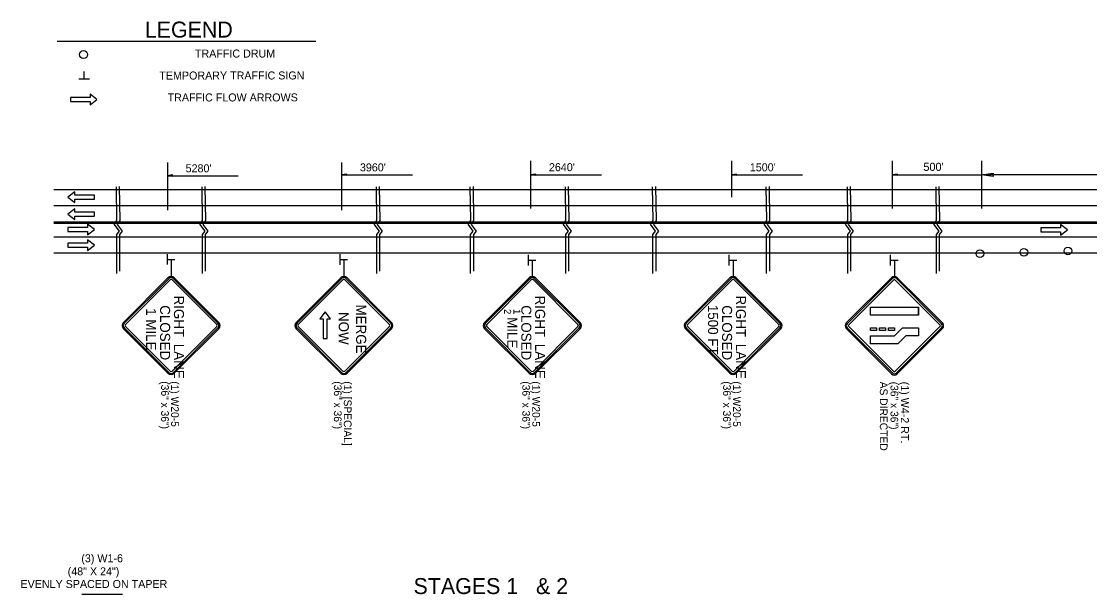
# Model space of a CAD drawing. Extents: x 1930579 to 1937984, y 596452 to 597630.
# Drawn here: x 1933731 to 1934532, y 597187 to 597617 of the extents above; entities that cross this region are included whole.
import ezdxf

# ---------------------------------------------------------------- set-up
doc = ezdxf.new("R2010")
doc.units = 0
for name, color, linetype in [('Default', 7, 'Continuous'), ('P_TC_Signs_Permanent', 7, 'Continuous'), ('P_TC_Signs_Temporary', 7, 'Continuous'), ('R_Border', 7, 'Continuous'), ('R_MOT', 7, 'Continuous'), ('R_Striping', 7, 'Continuous')]:
    doc.layers.add(name, color=color, linetype=linetype)

msp = doc.modelspace()

# ---------------------------------------------------------------- linework, layer by layer
at = {"layer": 'Default'}
for p, q in [((1933840.51, 597510.73), (1933840.51, 597474.82)), ((1933971.24, 597510.73), (1933971.24, 597474.82)), ((1934112.98, 597511.96), (1934112.98, 597476.04)), ((1934263.62, 597511.96), (1934263.62, 597484.57)), ((1934384.19, 597511.96), (1934384.19, 597476.04)), ((1934450.97, 597511.96), (1934450.97, 597476.04)), ((1933844.34, 597501.32), (1933840.51, 597500.75)), ((1933840.51, 597500.75), (1933893.74, 597500.75)), ((1933844.34, 597500.17), (1933840.51, 597500.75)), ((1933844.34, 597501.23), (1933841.15, 597500.75)), ((1933844.34, 597500.27), (1933841.15, 597500.75)), ((1933844.34, 597501.13), (1933841.81, 597500.75)), ((1933844.34, 597500.37), (1933841.81, 597500.75)), ((1933844.34, 597501.03), (1933842.45, 597500.75)), ((1933844.34, 597500.46), (1933842.45, 597500.75)), ((1933844.34, 597500.94), (1933843.09, 597500.75)), ((1933844.34, 597500.56), (1933843.09, 597500.75)), ((1933844.34, 597500.84), (1933843.73, 597500.75)), ((1933844.34, 597500.66), (1933843.73, 597500.75)), ((1933844.34, 597500.17), (1933844.34, 597501.32)), ((1933975.06, 597502), (1933971.24, 597501.43)), ((1933971.24, 597501.43), (1934024.47, 597501.43)), ((1933975.06, 597500.85), (1933971.24, 597501.43)), ((1933975.06, 597501.91), (1933971.88, 597501.43)), ((1933975.06, 597500.95), (1933971.88, 597501.43)), ((1933975.06, 597501.81), (1933972.53, 597501.43)), ((1933975.06, 597501.05), (1933972.53, 597501.43)), ((1933975.06, 597501.71), (1933973.17, 597501.43)), ((1933975.06, 597501.14), (1933973.17, 597501.43)), ((1933975.06, 597501.62), (1933973.82, 597501.43)), ((1933975.06, 597501.24), (1933973.82, 597501.43)), ((1933975.06, 597501.52), (1933974.46, 597501.43)), ((1933975.06, 597501.34), (1933974.46, 597501.43)), ((1933975.06, 597500.85), (1933975.06, 597502)), ((1934116.81, 597502), (1934112.98, 597501.43)), ((1934112.98, 597501.43), (1934166.22, 597501.43)), ((1934116.81, 597500.85), (1934112.98, 597501.43)), ((1934116.81, 597501.91), (1934113.62, 597501.43)), ((1934116.81, 597500.95), (1934113.62, 597501.43)), ((1934116.81, 597501.81), (1934114.28, 597501.43)), ((1934116.81, 597501.05), (1934114.28, 597501.43)), ((1934116.81, 597501.71), (1934114.92, 597501.43)), ((1934116.81, 597501.14), (1934114.92, 597501.43)), ((1934116.81, 597501.62), (1934115.57, 597501.43)), ((1934116.81, 597501.24), (1934115.57, 597501.43)), ((1934116.81, 597501.52), (1934116.2, 597501.43)), ((1934116.81, 597501.34), (1934116.2, 597501.43)), ((1934116.81, 597500.85), (1934116.81, 597502)), ((1934267.45, 597502), (1934263.62, 597501.43)), ((1934263.62, 597501.43), (1934316.85, 597501.43)), ((1934267.45, 597500.85), (1934263.62, 597501.43)), ((1934267.45, 597501.91), (1934264.26, 597501.43)), ((1934267.45, 597500.95), (1934264.26, 597501.43)), ((1934267.45, 597501.81), (1934264.92, 597501.43)), ((1934267.45, 597501.05), (1934264.92, 597501.43)), ((1934267.45, 597501.71), (1934265.55, 597501.43)), ((1934267.45, 597501.14), (1934265.55, 597501.43)), ((1934267.45, 597501.62), (1934266.2, 597501.43)), ((1934267.45, 597501.24), (1934266.2, 597501.43)), ((1934267.45, 597501.52), (1934266.84, 597501.43)), ((1934267.45, 597501.34), (1934266.84, 597501.43)), ((1934267.45, 597500.85), (1934267.45, 597502)), ((1934388.01, 597502), (1934384.19, 597501.43)), ((1934384.19, 597501.43), (1934450.97, 597501.43)), ((1934388.01, 597500.85), (1934384.19, 597501.43)), ((1934388.01, 597501.91), (1934384.83, 597501.43)), ((1934388.01, 597500.95), (1934384.83, 597501.43)), ((1934388.01, 597501.81), (1934385.48, 597501.43)), ((1934388.01, 597501.05), (1934385.48, 597501.43)), ((1934388.01, 597501.71), (1934386.12, 597501.43)), ((1934388.01, 597501.14), (1934386.12, 597501.43)), ((1934388.01, 597501.62), (1934386.77, 597501.43)), ((1934388.01, 597501.24), (1934386.77, 597501.43)), ((1934388.01, 597501.52), (1934387.41, 597501.43)), ((1934388.01, 597501.34), (1934387.41, 597501.43)), ((1934388.01, 597500.85), (1934388.01, 597502)), ((1934450.97, 597501.43), (1934459.83, 597502.76)), ((1934818.18, 597501.43), (1934450.97, 597501.43)), ((1934459.83, 597500.1), (1934450.97, 597501.43)), ((1934459.83, 597502.76), (1934459.83, 597500.1)), ((1935069.92, 597490.19), (1933755.41, 597490.19)), ((1935069.92, 597478.19), (1933755.41, 597478.19)), ((1935069.92, 597465.96), (1933755.41, 597465.96)), ((1935069.92, 597464.81), (1933755.41, 597464.81)), ((1935069.92, 597454.63), (1933755.41, 597454.63)), ((1935069.92, 597442.63), (1933755.41, 597442.63)), ((1933840.51, 597434.03), (1933840.51, 597442.01)), ((1933840.63, 597438), (1933846.08, 597438)), ((1933970.06, 597433.97), (1933970.06, 597441.95)), ((1933970.18, 597437.94), (1933975.63, 597437.94)), ((1934111.37, 597433.52), (1934111.37, 597441.5)), ((1934111.48, 597437.49), (1934116.93, 597437.49)), ((1934261.94, 597433.52), (1934261.94, 597441.5)), ((1934262.06, 597437.49), (1934267.51, 597437.49)), ((1934382.9, 597433.52), (1934382.9, 597441.5)), ((1934383.02, 597437.49), (1934388.47, 597437.49))]:
    msp.add_line(p, q, dxfattribs=at)
for points in [[(1933804.45, 597492.71), (1933804.84, 597467.14), (1933802.89, 597464.24), (1933806.68, 597459.04), (1933804.68, 597456.64), (1933804.68, 597429.08)], [(1933868.69, 597492.71), (1933869.08, 597467.14), (1933867.13, 597464.24), (1933870.92, 597459.04), (1933868.93, 597456.64), (1933868.92, 597429.08)], [(1933999.41, 597492.71), (1933999.8, 597467.14), (1933997.85, 597464.24), (1934001.65, 597459.04), (1933999.65, 597456.64), (1933999.65, 597429.08)], [(1934069.8, 597492.71), (1934070.18, 597467.14), (1934068.24, 597464.24), (1934072.03, 597459.04), (1934070.03, 597456.64), (1934070.03, 597429.08)], [(1934141.16, 597492.71), (1934141.55, 597467.14), (1934139.6, 597464.24), (1934143.4, 597459.04), (1934141.4, 597456.64), (1934141.39, 597429.08)], [(1934206.6, 597492.71), (1934206.99, 597467.14), (1934205.04, 597464.24), (1934208.84, 597459.04), (1934206.84, 597456.64), (1934206.84, 597429.08)], [(1934291.8, 597492.71), (1934292.18, 597467.14), (1934290.24, 597464.24), (1934294.03, 597459.04), (1934292.03, 597456.64), (1934292.03, 597429.08)], [(1934352.68, 597492.71), (1934353.07, 597467.14), (1934351.12, 597464.24), (1934354.92, 597459.04), (1934352.92, 597456.64), (1934352.91, 597429.08)], [(1934419.14, 597492.71), (1934419.53, 597467.14), (1934417.58, 597464.24), (1934421.37, 597459.04), (1934419.37, 597456.64), (1934419.37, 597429.08)], [(1933802.05, 597492.48), (1933802.44, 597467.24), (1933800.49, 597464.34), (1933804.29, 597459.14), (1933802.29, 597456.74), (1933802.28, 597427.4)], [(1933866.3, 597492.48), (1933866.68, 597467.24), (1933864.73, 597464.34), (1933868.53, 597459.14), (1933866.53, 597456.74), (1933866.52, 597427.4)], [(1933997.02, 597492.48), (1933997.4, 597467.24), (1933995.46, 597464.34), (1933999.25, 597459.14), (1933997.25, 597456.74), (1933997.25, 597427.4)], [(1934067.4, 597492.48), (1934067.79, 597467.24), (1934065.84, 597464.34), (1934069.64, 597459.14), (1934067.64, 597456.74), (1934067.63, 597427.4)], [(1934138.77, 597492.48), (1934139.15, 597467.24), (1934137.2, 597464.34), (1934141, 597459.14), (1934139, 597456.74), (1934138.99, 597427.4)], [(1934204.21, 597492.48), (1934204.59, 597467.24), (1934202.64, 597464.34), (1934206.44, 597459.14), (1934204.44, 597456.74), (1934204.44, 597427.4)], [(1934289.4, 597492.48), (1934289.79, 597467.24), (1934287.84, 597464.34), (1934291.64, 597459.14), (1934289.64, 597456.74), (1934289.63, 597427.4)], [(1934350.29, 597492.48), (1934350.67, 597467.24), (1934348.72, 597464.34), (1934352.52, 597459.14), (1934350.52, 597456.74), (1934350.52, 597427.4)], [(1934416.74, 597492.48), (1934417.13, 597467.24), (1934415.18, 597464.34), (1934418.98, 597459.14), (1934416.98, 597456.74), (1934416.97, 597427.4)]]:
    msp.add_lwpolyline(points, dxfattribs=at)
for centre, radius in [((1933777.66, 597591.57), 3), ((1934449.89, 597442.25), 2.87), ((1934482.87, 597443.3), 2.87), ((1934515.86, 597444.34), 2.87)]:
    msp.add_circle(centre, radius, dxfattribs=at)
at = {"layer": 'P_TC_Signs_Permanent'}
for p, q in [((1934349.68, 597390.32), (1934383.62, 597424.26)), ((1934403.75, 597396.24), (1934403.75, 597402.24)), ((1934383.62, 597352.14), (1934349.68, 597386.08)), ((1934421.81, 597386.08), (1934387.87, 597352.14)), ((1933806.82, 597186.52), (1933776.45, 597186.52))]:
    msp.add_line(p, q, dxfattribs=at)
for points in [[(1934384.26, 597423.63), (1934350.32, 597389.68)], [(1934351.38, 597388.62), (1934385.32, 597422.56)], [(1934386.17, 597422.56), (1934420.11, 597388.62)], [(1934421.17, 597389.68), (1934387.23, 597423.63)], [(1934387.87, 597424.26), (1934404.84, 597407.29), (1934421.81, 597390.32)], [(1934350.32, 597386.71), (1934384.26, 597352.77)], [(1934385.32, 597353.83), (1934351.38, 597387.78)], [(1934420.11, 597387.78), (1934386.17, 597353.83)], [(1934387.23, 597352.77), (1934421.17, 597386.71)]]:
    msp.add_lwpolyline(points, dxfattribs=at)
for points in [[(1934367.75, 597396.24), (1934367.75, 597402.24), (1934403.75, 597402.24), (1934403.75, 597396.24)], [(1934367.75, 597384.6), (1934367.75, 597386.7), (1934372.25, 597386.7), (1934372.25, 597384.6)], [(1934367.75, 597374.7), (1934367.75, 597380.7), (1934385.75, 597380.7), (1934391.75, 597386.7), (1934403.75, 597386.7), (1934403.75, 597380.7), (1934394.23, 597380.7), (1934388.23, 597374.7)], [(1934374.5, 597384.6), (1934374.5, 597386.7), (1934379, 597386.7), (1934379, 597384.6)], [(1934381.25, 597384.6), (1934381.25, 597386.7), (1934385.75, 597386.7), (1934385.75, 597384.6)]]:
    msp.add_lwpolyline(points, close=True, dxfattribs=at)
for centre, radius, start, end in [((1934385.75, 597422.14), 3, 45, 135), ((1934385.75, 597422.14), 2.1, 45, 135), ((1934385.75, 597422.14), 0.6, 45, 135), ((1934351.8, 597388.2), 3, 135, 225), ((1934351.8, 597388.2), 2.1, 135, 225), ((1934351.8, 597388.2), 0.6, 135, 225), ((1934419.69, 597388.2), 0.6, 315, 45), ((1934419.69, 597388.2), 2.1, 315, 45), ((1934419.69, 597388.2), 3, 315, 45), ((1934385.75, 597354.26), 3, 225, 315), ((1934385.75, 597354.26), 2.1, 225, 315), ((1934385.75, 597354.26), 0.6, 225, 315)]:
    msp.add_arc(centre, radius, start, end, dxfattribs=at)
at = {"layer": 'P_TC_Signs_Temporary'}
for p, q in [((1933807.56, 597390.74), (1933840.97, 597424.15)), ((1933808.22, 597390.08), (1933841.63, 597423.49)), ((1933809.15, 597389.15), (1933842.56, 597422.56)), ((1933844.15, 597422.56), (1933877.56, 597389.15)), ((1933845.08, 597423.49), (1933878.49, 597390.08)), ((1933845.74, 597424.15), (1933879.15, 597390.74)), ((1933937.11, 597390.74), (1933970.52, 597424.15)), ((1933937.77, 597390.08), (1933971.18, 597423.49)), ((1933938.7, 597389.15), (1933972.11, 597422.56)), ((1933973.7, 597422.56), (1934007.11, 597389.15)), ((1933974.63, 597423.49), (1934008.04, 597390.08)), ((1933975.29, 597424.15), (1934008.7, 597390.74)), ((1934078.41, 597390.74), (1934111.82, 597424.15)), ((1934079.07, 597390.08), (1934112.48, 597423.49)), ((1934080, 597389.15), (1934113.41, 597422.56)), ((1934115, 597422.56), (1934148.41, 597389.15)), ((1934115.93, 597423.49), (1934149.34, 597390.08)), ((1934116.59, 597424.15), (1934150, 597390.74)), ((1934228.99, 597390.74), (1934262.4, 597424.15)), ((1934229.65, 597390.08), (1934263.06, 597423.49)), ((1934230.58, 597389.15), (1934263.99, 597422.56)), ((1934265.58, 597422.56), (1934298.99, 597389.15)), ((1934266.51, 597423.49), (1934299.92, 597390.08)), ((1934267.17, 597424.15), (1934300.58, 597390.74)), ((1933840.97, 597352.56), (1933807.56, 597385.97)), ((1933841.63, 597353.22), (1933808.22, 597386.63)), ((1933842.56, 597354.15), (1933809.15, 597387.56)), ((1933877.56, 597387.56), (1933844.15, 597354.15)), ((1933878.49, 597386.63), (1933845.08, 597353.22)), ((1933879.15, 597385.97), (1933845.74, 597352.56)), ((1933970.52, 597352.56), (1933937.11, 597385.97)), ((1933971.18, 597353.22), (1933937.77, 597386.63)), ((1933972.11, 597354.15), (1933938.7, 597387.56)), ((1934007.11, 597387.56), (1933973.7, 597354.15)), ((1934008.04, 597386.63), (1933974.63, 597353.22)), ((1934008.7, 597385.97), (1933975.29, 597352.56)), ((1934111.82, 597352.56), (1934078.41, 597385.97)), ((1934112.48, 597353.22), (1934079.07, 597386.63)), ((1934113.41, 597354.15), (1934080, 597387.56)), ((1934148.41, 597387.56), (1934115, 597354.15)), ((1934149.34, 597386.63), (1934115.93, 597353.22)), ((1934150, 597385.97), (1934116.59, 597352.56)), ((1934262.4, 597352.56), (1934228.99, 597385.97)), ((1934263.06, 597353.22), (1934229.65, 597386.63)), ((1934263.99, 597354.15), (1934230.58, 597387.56)), ((1934298.99, 597387.56), (1934265.58, 597354.15)), ((1934299.92, 597386.63), (1934266.51, 597353.22)), ((1934300.58, 597385.97), (1934267.17, 597352.56))]:
    msp.add_line(p, q, dxfattribs=at)
for centre, radius, start, end in [((1933843.35, 597421.77), 3.37, 45, 135), ((1933843.35, 597421.77), 2.44, 45, 135), ((1933843.35, 597421.77), 1.12, 45, 135), ((1933972.9, 597421.77), 3.37, 45, 135), ((1933972.9, 597421.77), 2.44, 45, 135), ((1933972.9, 597421.77), 1.12, 45, 135), ((1934114.21, 597421.77), 3.37, 45, 135), ((1934114.21, 597421.77), 2.44, 45, 135), ((1934114.21, 597421.77), 1.12, 45, 135), ((1934264.78, 597421.77), 3.37, 45, 135), ((1934264.78, 597421.77), 2.44, 45, 135), ((1934264.78, 597421.77), 1.12, 45, 135), ((1933809.94, 597388.35), 3.37, 135, 225), ((1933809.94, 597388.35), 2.44, 135, 225), ((1933809.94, 597388.35), 1.13, 135, 225), ((1933876.76, 597388.35), 1.13, 315, 45), ((1933876.76, 597388.35), 2.44, 315, 45), ((1933876.76, 597388.35), 3.38, 315, 45), ((1933939.49, 597388.35), 3.37, 135, 225), ((1933939.49, 597388.35), 2.44, 135, 225), ((1933939.49, 597388.35), 1.13, 135, 225), ((1934006.32, 597388.35), 1.13, 315, 45), ((1934006.32, 597388.35), 2.44, 315, 45), ((1934006.32, 597388.35), 3.38, 315, 45), ((1934080.8, 597388.35), 3.37, 135, 225), ((1934080.8, 597388.35), 2.44, 135, 225), ((1934080.8, 597388.35), 1.13, 135, 225), ((1934147.62, 597388.35), 1.13, 315, 45), ((1934147.62, 597388.35), 2.44, 315, 45), ((1934147.62, 597388.35), 3.38, 315, 45), ((1934231.37, 597388.35), 3.37, 135, 225), ((1934231.37, 597388.35), 2.44, 135, 225), ((1934231.37, 597388.35), 1.13, 135, 225), ((1934298.2, 597388.35), 1.13, 315, 45), ((1934298.2, 597388.35), 2.44, 315, 45), ((1934298.2, 597388.35), 3.38, 315, 45), ((1933843.35, 597354.94), 3.38, 225, 315), ((1933843.35, 597354.94), 2.44, 225, 315), ((1933843.35, 597354.94), 1.12, 225, 315), ((1933972.9, 597354.94), 3.38, 225, 315), ((1933972.9, 597354.94), 2.44, 225, 315), ((1933972.9, 597354.94), 1.12, 225, 315), ((1934114.21, 597354.94), 3.38, 225, 315), ((1934114.21, 597354.94), 2.44, 225, 315), ((1934114.21, 597354.94), 1.12, 225, 315), ((1934264.78, 597354.94), 3.38, 225, 315), ((1934264.78, 597354.94), 2.44, 225, 315), ((1934264.78, 597354.94), 1.12, 225, 315)]:
    msp.add_arc(centre, radius, start, end, dxfattribs=at)
at = {"layer": 'R_Border'}
for p, q in [((1933757.88, 597601.6), (1933951.8, 597601.73)), ((1933782.02, 597573.29), (1933774.02, 597573.28)), ((1933778.04, 597573.4), (1933778.04, 597578.86)), ((1933843.35, 597438), (1933843.35, 597425.07)), ((1933972.9, 597437.94), (1933972.9, 597425.14)), ((1934114.21, 597437.49), (1934114.21, 597425.14)), ((1934264.78, 597437.49), (1934264.78, 597425.14)), ((1934385.75, 597437.49), (1934385.75, 597425.14))]:
    msp.add_line(p, q, dxfattribs=at)
at = {"layer": 'R_MOT'}
for points in [[(1933782.53, 597553.89), (1933787.72, 597557.89), (1933782.53, 597561.89), (1933782.53, 597559.39), (1933767.82, 597559.38), (1933767.82, 597556.38), (1933782.53, 597556.39)], [(1933962.77, 597393.38), (1933958.77, 597398.57), (1933954.77, 597393.38), (1933957.27, 597393.38), (1933957.27, 597378.67), (1933960.27, 597378.67), (1933960.27, 597393.38)]]:
    msp.add_lwpolyline(points, close=True, dxfattribs=at)
at = {"layer": 'R_Striping'}
for points in [[(1933771.14, 597488.56), (1933765.95, 597484.56), (1933771.14, 597480.56), (1933771.14, 597483.06), (1933785.85, 597483.06), (1933785.85, 597486.06), (1933771.14, 597486.06)], [(1933771.14, 597475.92), (1933765.95, 597471.92), (1933771.14, 597467.92), (1933771.14, 597470.42), (1933785.85, 597470.42), (1933785.85, 597473.42), (1933771.14, 597473.42)], [(1933780.66, 597456.42), (1933785.85, 597460.42), (1933780.66, 597464.42), (1933780.66, 597461.92), (1933765.95, 597461.92), (1933765.95, 597458.92), (1933780.66, 597458.92)], [(1934510.28, 597456.05), (1934515.47, 597460.05), (1934510.28, 597464.05), (1934510.28, 597461.55), (1934495.57, 597461.55), (1934495.57, 597458.55), (1934510.28, 597458.55)], [(1933780.66, 597444.64), (1933785.85, 597448.64), (1933780.66, 597452.64), (1933780.66, 597450.14), (1933765.95, 597450.14), (1933765.95, 597447.14), (1933780.66, 597447.14)]]:
    msp.add_lwpolyline(points, close=True, dxfattribs=at)

# ---------------------------------------------------------------- texts
at = {"layer": 'Default'}
for s, height, p in [("5280'", 6, (1933854.23, 597503.32)), ("3960'", 6, (1933984.95, 597503.99)), ("2640'", 6, (1934126.7, 597504.15)), ("1500'", 6, (1934277.34, 597504.06)), ("500'", 6.12, (1934407.48, 597504.34)), ('STAGES 1   & 2', 12, (1934025.15, 597186.95))]:
    msp.add_text(s, height=height, rotation=360, dxfattribs=at).set_placement(p)
at = {"layer": 'P_TC_Signs_Temporary'}
for s, height, p in [('RIGHT\u2002LANE', 7.5, (1933845.48, 597410.88)), ('RIGHT\u2002LANE', 7.5, (1934116.33, 597410.88)), ('RIGHT\u2002LANE', 7.5, (1934266.91, 597410.88)), ('1 MILE', 7.5, (1933824.6, 597401.41)), ('CLOSED', 7.5, (1933835.1, 597403.61)), ('NOW', 7.5, (1933969.09, 597398.52)), ('MERGE', 7.5, (1933982.12, 597404.11)), ('2', 5.25, (1934093.08, 597400.71)), ('1', 5.25, (1934100.08, 597400.71)), ('CLOSED', 7.5, (1934105.96, 597403.61)), ('1500 FT', 7.5, (1934246.03, 597403.88)), ('CLOSED', 7.5, (1934256.53, 597403.61)), (' MILE', 7.5, (1934095.46, 597397.45))]:
    msp.add_text(s, height=height, rotation=270, dxfattribs=at).set_placement(p)
at = {"layer": 'R_Border'}
for s, height, rotation, p in [('LEGEND', 12, 0.03878, (1933823.62, 597604.33)), ('TRAFFIC DRUM', 6, 0.03876, (1933861.2, 597589.37)), ('TEMPORARY TRAFFIC SIGN', 6, 0.03876, (1933834.53, 597572.89)), ('TRAFFIC FLOW ARROWS', 6, 0.03876, (1933840.74, 597556.43)), ('(36" x 36")', 5.76, 270, (1933835.86, 597346.58)), ('(1) W20-5', 5.76, 270, (1933843.35, 597346.58)), ('(36" x 36")', 5.76, 270, (1933965.42, 597346.57)), ('(1) [SPECIAL]', 5.76, 270, (1933972.9, 597346.57)), ('(36" x 36")', 5.76, 270, (1934106.72, 597346.57)), ('(1) W20-5', 5.76, 270, (1934114.21, 597346.57)), ('(36" x 36")', 5.76, 270, (1934257.3, 597346.57)), ('(1) W20-5', 5.76, 270, (1934264.78, 597346.57)), ('AS DIRECTED ', 5.76, 270, (1934374.86, 597346.26)), ('(36" x 36")', 5.76, 270, (1934382.87, 597346.26)), ('(1) W4-2 RT.', 6, 270, (1934390.63, 597346.26)), ('(3) W1-6', 6, 0.00754, (1933776.02, 597210.8)), ('(48" X 24")', 6, 0.00754, (1933765.79, 597201)), ('EVENLY SPACED ON TAPER', 6, 0.00754, (1933730.38, 597191.5))]:
    msp.add_text(s, height=height, rotation=rotation, dxfattribs=at).set_placement(p)

doc.saveas('drawing.dxf')
